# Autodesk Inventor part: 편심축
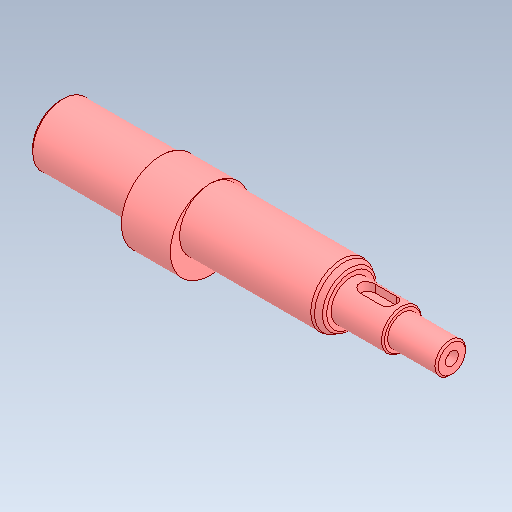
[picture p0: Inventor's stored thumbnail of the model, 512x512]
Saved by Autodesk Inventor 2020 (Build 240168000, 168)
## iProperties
Created: 2024-08
Part Number: 편심축
Material: 강철, 탄소
Document SubType Name: Modeling
Designer: oem
Density: 7.85 g/cm^3
Appearance: 기본값
Author: jhkim
Sending System: Autodesk Inventor 2025
Preprocessor: ST-DEVELOPER v20
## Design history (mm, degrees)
node "편심축1"
node "솔리드2"
node "솔리드1"
